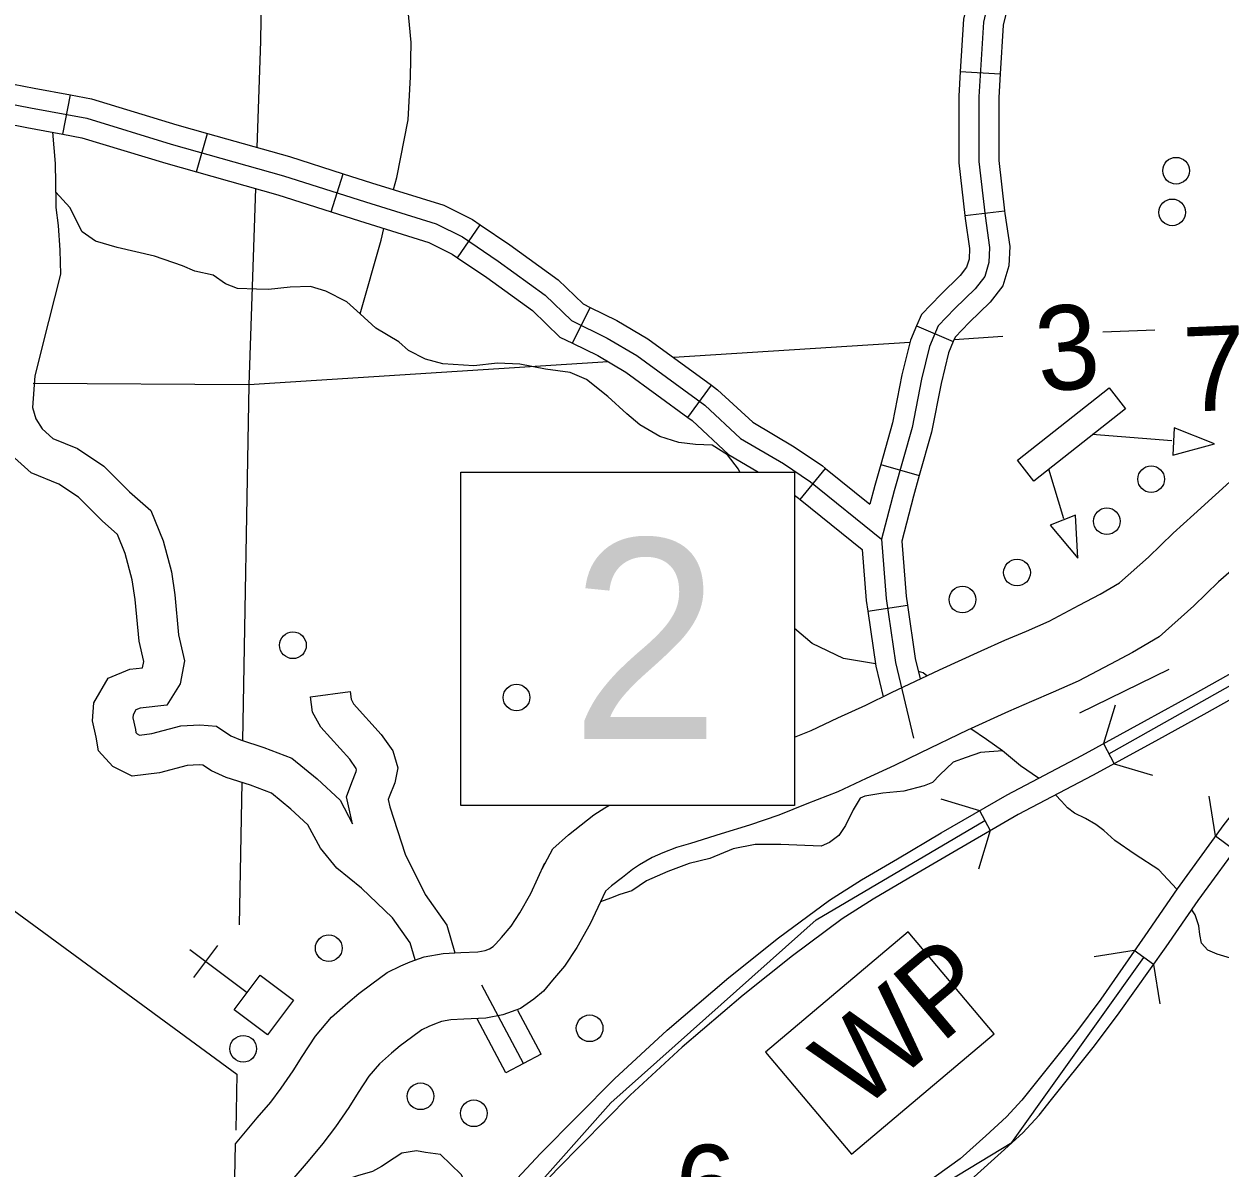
# Model space of a CAD drawing. Extents: x 22866 to 28196, y 1324810 to 1328105.
# Drawn here: x 25197.3 to 25304.9, y 1326082.2 to 1326185.2 of the extents above; entities that cross this region are included whole.
import ezdxf

# ---------------------------------------------------------------- set-up
doc = ezdxf.new("R2010")
doc.units = 0
for name, color, linetype in [('Default', 7, 'Continuous'), ('Level 10', 7, 'Continuous'), ('Level 19', 7, 'Continuous'), ('Level 31', 7, 'Continuous'), ('Level 32', 7, 'Continuous'), ('Level 35', 7, 'Continuous'), ('Level 39', 7, 'Continuous'), ('Level 45', 7, 'Continuous'), ('Level 46', 7, 'Continuous'), ('Level 5', 7, 'Continuous'), ('Level 56', 7, 'Continuous'), ('Level 57', 7, 'Continuous'), ('Level 63', 7, 'Continuous')]:
    doc.layers.add(name, color=color, linetype=linetype)

msp = doc.modelspace()

# ---------------------------------------------------------------- linework, layer by layer
at = {"layer": 'Default'}
for p, q in [((25294.91, 1326119.53), (25321.82, 1326134.66)), ((25268.58, 1326104.59), (25283.76, 1326113.52)), ((25250.12, 1326088.11), (25268.58, 1326104.59)), ((25286.19, 1326084.53), (25298.07, 1326101.19)), ((25233.67, 1326069.64), (25250.12, 1326088.11)), ((25267.72, 1326073.42), (25286.19, 1326084.53))]:
    msp.add_line(p, q, dxfattribs=at)
msp.add_lwpolyline([(25236.63, 1326144.87), (25266.63, 1326144.87), (25266.63, 1326114.87), (25236.63, 1326114.87)], close=True, dxfattribs=at)
msp.add_lwpolyline([(25236.63, 1326144.87), (25266.63, 1326144.87), (25266.63, 1326114.87), (25236.63, 1326114.87)], close=True, dxfattribs=at)
at = {"layer": 'Level 10'}
msp.add_line((25216.19, 1326075.25), (25216.35, 1326084.43), dxfattribs=at)
for points in [[(25184.79, 1326187.58), (25185.09, 1326186.26), (25185.6, 1326185.4), (25187.75, 1326183.63), (25189.56, 1326182.02), (25191.56, 1326180.21), (25193.29, 1326178.96), (25195.91, 1326178.05), (25197.91, 1326177.67), (25202.97, 1326176.72), (25210.58, 1326174.4)], [(25210.58, 1326174.4), (25220.68, 1326171.55), (25228.06, 1326169.19), (25234.41, 1326167.23), (25236.77, 1326166.05), (25239.98, 1326163.85), (25244.22, 1326160.79), (25246.57, 1326158.51), (25249.79, 1326156.94), (25252.46, 1326155.37), (25258.58, 1326150.9), (25261.79, 1326147.91), (25265.64, 1326145.64), (25268.07, 1326143.99), (25274.46, 1326138.83)], [(25266.63, 1326121.02), (25268.14, 1326121.62), (25270.54, 1326122.75), (25273.05, 1326123.91), (25275.36, 1326125.03), (25279.67, 1326127.09), (25283.44, 1326128.8), (25285.57, 1326129.74), (25287.5, 1326130.57), (25289.53, 1326131.46), (25292.25, 1326132.9), (25294.12, 1326133.88), (25295.87, 1326134.92), (25298.47, 1326137.23), (25300.7, 1326139.39), (25302.57, 1326141.06), (25306.45, 1326144.59)], [(25306.59, 1326136.6), (25304.78, 1326134.99), (25302.56, 1326132.84), (25299.44, 1326130.05), (25297.05, 1326128.63), (25295.05, 1326127.59), (25292.15, 1326126.05), (25289.89, 1326125.06), (25287.96, 1326124.23), (25285.89, 1326123.32), (25282.21, 1326121.65), (25277.97, 1326119.62), (25275.62, 1326118.48), (25273.08, 1326117.31), (25270.52, 1326116.11), (25267.74, 1326115.01), (25265.23, 1326114.01), (25262.6, 1326113.11), (25260.05, 1326112.31), (25257.29, 1326111.46), (25256.02, 1326111.08), (25254.8, 1326110.62), (25253.83, 1326110.2), (25252.7, 1326109.53), (25252.06, 1326109.12), (25251.15, 1326108.4), (25250.16, 1326107.64), (25249.63, 1326107.15)], [(25243.95, 1326109.18), (25244.9, 1326110.96), (25246.3, 1326112.24), (25247.45, 1326113.12), (25248.59, 1326114.04), (25249.58, 1326114.65), (25249.95, 1326114.87)], [(25223.54, 1326094.1), (25225, 1326095.83), (25226.47, 1326097.12), (25227.45, 1326097.95), (25228.62, 1326098.82), (25230, 1326099.83), (25231.24, 1326100.44), (25232.08, 1326100.79), (25233.31, 1326101.24), (25235.04, 1326101.56), (25236.62, 1326101.63), (25238.15, 1326101.69), (25238.81, 1326101.82), (25239.21, 1326101.97), (25239.53, 1326102.19), (25239.78, 1326102.41), (25240.29, 1326103), (25241.14, 1326104.02), (25241.94, 1326105.22), (25242.91, 1326106.95), (25244.19, 1326109.7)], [(25249.63, 1326107.15), (25248.25, 1326104.21), (25247.06, 1326102.08), (25245.95, 1326100.42), (25244.88, 1326099.14), (25244.05, 1326098.16), (25243.2, 1326097.43), (25241.98, 1326096.59), (25240.41, 1326096.02), (25238.87, 1326095.72), (25236.89, 1326095.63), (25235.72, 1326095.58), (25234.89, 1326095.43), (25234.26, 1326095.2), (25233.73, 1326094.98), (25233.12, 1326094.68), (25232.18, 1326093.99), (25231.18, 1326093.25), (25230.39, 1326092.58), (25229.3, 1326091.62), (25228.36, 1326090.5)], [(25216.35, 1326084.43), (25218.3, 1326086.76), (25219.53, 1326088.18), (25220.46, 1326089.44), (25221.53, 1326090.99), (25222.35, 1326092.29), (25223.54, 1326094.1)], [(25228.36, 1326090.5), (25227.39, 1326089.04), (25226.55, 1326087.7), (25225.34, 1326085.94), (25224.22, 1326084.44), (25222.88, 1326082.87), (25221.42, 1326081.14), (25219.28, 1326078.62), (25217.76, 1326076.97)]]:
    msp.add_lwpolyline(points, dxfattribs=at)
at = {"layer": 'Level 19'}
for points in [[(25302.72, 1326124.98), (25310.15, 1326129.15), (25315.19, 1326132.18), (25315.37, 1326132.34)], [(25316.47, 1326130.68), (25316.4, 1326130.63), (25311.16, 1326127.38), (25303.72, 1326123.2)], [(25318.65, 1326128.4), (25317.58, 1326127.33), (25314.63, 1326124.17), (25311.4, 1326120.55), (25307.94, 1326116.57), (25305.26, 1326113.16), (25301.05, 1326107.37), (25298.14, 1326103.15), (25294.2, 1326097.43)], [(25295.83, 1326096.2), (25300.06, 1326102.15), (25302.95, 1326106.33), (25307.1, 1326112.03), (25309.67, 1326115.32), (25313.06, 1326119.21), (25316.24, 1326122.79), (25319.05, 1326125.79), (25319.79, 1326126.71)], [(25219.81, 1326056.48), (25218.48, 1326058.03), (25223.62, 1326062.78), (25232.2, 1326071.06), (25233.75, 1326072.77), (25243.8, 1326083.55), (25250.43, 1326090.27), (25255.19, 1326094.64), (25260.72, 1326099.38), (25265.21, 1326102.96), (25269.77, 1326106.36), (25272.66, 1326108.19), (25275.89, 1326110.08), (25279.84, 1326112.41), (25285.78, 1326115.84), (25292.47, 1326119.37), (25298.13, 1326122.46), (25302.72, 1326124.98)], [(25303.72, 1326123.2), (25299.12, 1326120.67), (25293.43, 1326117.57), (25286.76, 1326114.06), (25280.87, 1326110.65), (25276.93, 1326108.32), (25273.72, 1326106.44), (25270.93, 1326104.68), (25266.45, 1326101.34), (25262.02, 1326097.8), (25256.54, 1326093.12), (25251.85, 1326088.8), (25245.28, 1326082.14), (25235.25, 1326071.39), (25233.67, 1326069.64), (25225.02, 1326061.29), (25219.81, 1326056.48)], [(25294.2, 1326097.43), (25292, 1326094.49), (25288.16, 1326089.69), (25287.08, 1326088.34), (25285.72, 1326086.86), (25283.85, 1326085.15), (25281.53, 1326083.06), (25278.23, 1326080.71), (25276.73, 1326079.74), (25274.1, 1326078.22), (25271.69, 1326077.1), (25269.43, 1326076.14), (25264.65, 1326074.56), (25259.94, 1326073), (25255.94, 1326071.72), (25252.61, 1326070.71), (25248.87, 1326069.47), (25245.88, 1326068.29), (25242.81, 1326066.99), (25239.52, 1326065.45), (25236.93, 1326064.23)], [(25237.8, 1326062.38), (25240.39, 1326063.6), (25243.64, 1326065.12), (25246.65, 1326066.4), (25249.57, 1326067.55), (25253.23, 1326068.77), (25256.54, 1326069.77), (25260.58, 1326071.06), (25265.29, 1326072.62), (25270.15, 1326074.23), (25272.53, 1326075.24), (25275.04, 1326076.41), (25277.8, 1326078), (25279.37, 1326079.02), (25282.81, 1326081.46), (25285.22, 1326083.64), (25287.16, 1326085.42), (25288.63, 1326087.01), (25289.75, 1326088.42), (25293.61, 1326093.24), (25295.83, 1326096.2)]]:
    msp.add_lwpolyline(points, dxfattribs=at)
at = {"layer": 'Level 31'}
for points in [[(25299.39, 1326224.03), (25302.07, 1326218.13), (25302.75, 1326215.52), (25302.82, 1326214.29), (25302.48, 1326212.16), (25301.45, 1326210.17), (25298.23, 1326205.78), (25294.18, 1326200.98), (25290.89, 1326198.44), (25289.04, 1326197.2), (25288.01, 1326195.94), (25285.61, 1326191.82), (25284.52, 1326189.15), (25283.63, 1326185.37), (25283.21, 1326178.65), (25283.21, 1326172.82), (25283.78, 1326167.93)], [(25283.78, 1326167.93), (25284.19, 1326165.08), (25284.12, 1326163.75), (25283.75, 1326162.48), (25282.89, 1326161.38), (25281.07, 1326159.6), (25279.57, 1326158.04), (25278.78, 1326156.19), (25278.06, 1326153.24), (25277.21, 1326148.88), (25275.6, 1326143.19), (25274.46, 1326138.83), (25274.88, 1326133.51), (25275.73, 1326127.75), (25277.34, 1326120.92)]]:
    msp.add_lwpolyline(points, dxfattribs=at)
at = {"layer": 'Level 32'}
for p, q in [((25281.55, 1326180.93), (25285.14, 1326180.71)), ((25200.83, 1326175.29), (25201.5, 1326178.83)), ((25212.86, 1326171.89), (25213.84, 1326175.35)), ((25224.95, 1326168.3), (25226.05, 1326171.73)), ((25281.96, 1326167.98), (25285.54, 1326168.39)), ((25236.33, 1326164.17), (25238.37, 1326167.14)), ((25246.67, 1326156.47), (25248.25, 1326159.7)), ((25277.61, 1326158.03), (25280.92, 1326156.62)), ((25257.03, 1326149.8), (25259.16, 1326152.71)), ((25267.16, 1326142.41), (25269.42, 1326145.21)), ((25274.4, 1326145.56), (25277.86, 1326144.58)), ((25273.23, 1326132.37), (25276.79, 1326132.9)), ((25243.85, 1326092.5), (25240.67, 1326090.81))]:
    msp.add_line(p, q, dxfattribs=at)
for points in [[(25284.74, 1326193.89), (25284, 1326192.62), (25282.8, 1326189.7), (25281.84, 1326185.64), (25281.55, 1326180.93)], [(25287.85, 1326192.08), (25287.23, 1326191.03), (25286.24, 1326188.6), (25285.41, 1326185.11), (25285.14, 1326180.71)], [(25190.97, 1326183.17), (25192.7, 1326181.61), (25194.13, 1326180.57), (25196.38, 1326179.8), (25198.25, 1326179.44), (25201.5, 1326178.83)], [(25188.56, 1326180.5), (25190.42, 1326178.81), (25192.44, 1326177.34), (25195.45, 1326176.31), (25197.58, 1326175.9), (25200.83, 1326175.29)], [(25281.55, 1326180.93), (25281.41, 1326178.71), (25281.41, 1326172.72), (25281.96, 1326167.98)], [(25285.14, 1326180.71), (25285.01, 1326178.6), (25285.01, 1326172.92), (25285.54, 1326168.39)], [(25201.5, 1326178.83), (25203.4, 1326178.47), (25211.09, 1326176.13), (25213.84, 1326175.35)], [(25200.83, 1326175.29), (25202.54, 1326174.97), (25210.08, 1326172.68), (25212.86, 1326171.89)], [(25213.84, 1326175.35), (25221.2, 1326173.27), (25226.05, 1326171.73)], [(25212.86, 1326171.89), (25220.17, 1326169.82), (25224.95, 1326168.3)], [(25226.05, 1326171.73), (25228.6, 1326170.91), (25235.09, 1326168.91), (25237.68, 1326167.61), (25238.37, 1326167.14)], [(25224.95, 1326168.3), (25227.52, 1326167.48), (25233.74, 1326165.55), (25235.85, 1326164.5), (25236.33, 1326164.17)], [(25281.96, 1326167.98), (25281.99, 1326167.7), (25282.38, 1326165), (25282.34, 1326164.05), (25282.12, 1326163.32), (25281.54, 1326162.58), (25279.79, 1326160.86), (25278.05, 1326159.05), (25277.61, 1326158.03)], [(25285.54, 1326168.39), (25285.57, 1326168.16), (25286, 1326165.17), (25285.91, 1326163.44), (25285.37, 1326161.64), (25284.24, 1326160.18), (25282.35, 1326158.33), (25281.1, 1326157.03), (25280.92, 1326156.62)], [(25238.37, 1326167.14), (25241.02, 1326165.33), (25245.38, 1326162.18), (25247.62, 1326160.01), (25248.25, 1326159.7)], [(25236.33, 1326164.17), (25238.95, 1326162.38), (25243.06, 1326159.41), (25245.53, 1326157.02), (25246.67, 1326156.47)], [(25248.25, 1326159.7), (25250.64, 1326158.53), (25253.45, 1326156.88), (25259.16, 1326152.71)], [(25277.61, 1326158.03), (25277.07, 1326156.76), (25276.3, 1326153.63), (25275.45, 1326149.3), (25274.4, 1326145.56)], [(25246.67, 1326156.47), (25248.94, 1326155.36), (25251.47, 1326153.87), (25257.03, 1326149.8)], [(25280.92, 1326156.62), (25280.5, 1326155.62), (25279.82, 1326152.85), (25278.96, 1326148.46), (25277.86, 1326144.58)], [(25259.16, 1326152.71), (25259.72, 1326152.29), (25262.88, 1326149.37), (25266.6, 1326147.16), (25269.14, 1326145.44), (25269.42, 1326145.21)], [(25257.03, 1326149.8), (25257.43, 1326149.51), (25260.71, 1326146.46), (25263.4, 1326144.87)], [(25269.42, 1326145.21), (25273.42, 1326141.98)], [(25274.4, 1326145.56), (25273.86, 1326143.66), (25273.42, 1326141.98)], [(25277.86, 1326144.58), (25277.33, 1326142.72), (25276.28, 1326138.67), (25276.67, 1326133.71), (25276.79, 1326132.9)], [(25266.63, 1326142.79), (25267, 1326142.54), (25267.16, 1326142.41)], [(25267.16, 1326142.41), (25272.73, 1326137.91)], [(25272.73, 1326137.91), (25273.09, 1326133.31), (25273.23, 1326132.37)], [(25273.23, 1326132.37), (25273.96, 1326127.41), (25274.61, 1326124.66)], [(25276.79, 1326132.9), (25277.5, 1326128.09), (25277.93, 1326126.26)], [(25242.26, 1326091.66), (25238.51, 1326098.71)], [(25240.67, 1326090.81), (25238.08, 1326095.68)], [(25243.85, 1326092.5), (25241.76, 1326096.43)]]:
    msp.add_lwpolyline(points, dxfattribs=at)
at = {"layer": 'Level 35'}
for points in [[(25230.58, 1326170.3), (25230.86, 1326171.39), (25231.9, 1326176.57), (25232.11, 1326180.45), (25232.16, 1326183.53), (25231.8, 1326187.35), (25231.27, 1326188.22), (25229.65, 1326189.84), (25228.19, 1326191.15), (25226.99, 1326193.14), (25224.27, 1326197.69), (25222.75, 1326201.93)], [(25226.37, 1326160.19), (25224.47, 1326161.17), (25223.09, 1326161.57), (25221.27, 1326161.52), (25219.32, 1326161.3), (25218.25, 1326161.34), (25216.52, 1326161.39), (25215.45, 1326161.83), (25214.34, 1326162.59), (25212.7, 1326162.95), (25211.59, 1326163.43), (25209.06, 1326164.32), (25205.72, 1326165.08), (25203.77, 1326165.66), (25202.57, 1326166.5), (25201.46, 1326168.68), (25200.18, 1326170.08)], [(25227.57, 1326159.12), (25229.45, 1326165.74), (25229.71, 1326166.8)], [(25261.72, 1326144.87), (25261.59, 1326145.14), (25260.62, 1326146.43), (25259.24, 1326147.31), (25257.73, 1326147.36), (25256.22, 1326147.54), (25254.53, 1326148.07), (25252.71, 1326149.14), (25251.55, 1326150.12), (25249.86, 1326151.67), (25247.92, 1326153.21), (25246.45, 1326153.83), (25244.23, 1326154.14), (25241.92, 1326154.59), (25239.92, 1326154.67), (25237.79, 1326154.45), (25234.99, 1326154.63), (25233.44, 1326155.03), (25231.93, 1326155.83), (25231.04, 1326156.59), (25228.99, 1326157.83), (25227.57, 1326159.12), (25226.37, 1326160.19)], [(25273.93, 1326127.61), (25271.05, 1326128.11), (25268.21, 1326129.44), (25266.63, 1326130.81)], [(25278.55, 1326126.54), (25278.21, 1326126.81), (25277.78, 1326126.92)], [(25288.57, 1326117.32), (25286.95, 1326118.43), (25285.34, 1326119.8), (25283.9, 1326120.81), (25282.49, 1326121.78)], [(25285.34, 1326119.8), (25283.37, 1326119.63), (25282.09, 1326119.2), (25280.92, 1326118.76), (25279.72, 1326117.62), (25279.05, 1326116.95), (25278.31, 1326116.65), (25276.47, 1326116.15), (25274.59, 1326115.98), (25272.95, 1326115.71), (25272.55, 1326115.54), (25271.91, 1326114.47), (25271.21, 1326113.06), (25270.61, 1326112.16), (25269.77, 1326111.55), (25269.03, 1326111.22)], [(25290.64, 1326115.25), (25290.1, 1326115.82)], [(25295.45, 1326111.71), (25294.46, 1326112.61), (25293.73, 1326113.16), (25292.81, 1326113.71), (25291.82, 1326114.18), (25291.19, 1326114.65), (25290.64, 1326115.25)], [(25301.03, 1326107.35), (25299.4, 1326109.07), (25297.28, 1326110.45), (25295.45, 1326111.71)], [(25269.03, 1326111.22), (25266.86, 1326111.29), (25265.42, 1326111.35), (25263.11, 1326111.35), (25261.13, 1326110.98), (25259.02, 1326110.11), (25257.15, 1326109.64), (25255.24, 1326108.94), (25253.33, 1326108.1), (25251.99, 1326107.2), (25250.92, 1326106.86), (25250.08, 1326106.52)], [(25250.08, 1326106.52), (25249.18, 1326106.2)], [(25303.02, 1326104.05), (25302.69, 1326105.04), (25302.37, 1326105.49)], [(25307.83, 1326095.74), (25307.21, 1326096.73), (25306.87, 1326097.75), (25306.87, 1326098.4), (25307.08, 1326099.14), (25306.97, 1326099.76), (25306.5, 1326100.52), (25305.85, 1326101.12), (25304.64, 1326101.49), (25303.83, 1326101.86), (25303.26, 1326102.48), (25303.1, 1326103.27), (25303.02, 1326104.05)]]:
    msp.add_lwpolyline(points, dxfattribs=at)
at = {"layer": 'Level 39'}
for p, q in [((25295.47, 1326123.9), (25294.43, 1326120.44)), ((25294.43, 1326120.44), (25295.39, 1326118.63)), ((25295.39, 1326118.63), (25298.85, 1326117.59)), ((25279.81, 1326115.48), (25283.28, 1326114.43)), ((25304.5, 1326112.13), (25303.94, 1326115.7)), ((25283.28, 1326114.43), (25284.24, 1326112.62)), ((25284.24, 1326112.62), (25283.18, 1326109.13)), ((25304.5, 1326112.13), (25306.25, 1326110.85)), ((25297.2, 1326101.82), (25293.6, 1326101.24)), ((25298.93, 1326100.56), (25297.2, 1326101.82)), ((25298.93, 1326100.56), (25299.5, 1326097.02))]:
    msp.add_line(p, q, dxfattribs=at)
at = {"layer": 'Level 45'}
msp.add_lwpolyline([(25236.82, 1326081.34), (25236.64, 1326081.66), (25234.79, 1326083.46), (25233.45, 1326083.63), (25232.63, 1326083.79), (25231.33, 1326083.57), (25230.64, 1326083.13), (25229.5, 1326082.39), (25228.69, 1326081.93), (25227.34, 1326081.53), (25226.89, 1326081.38)], dxfattribs=at)
at = {"layer": 'Level 46'}
for points in [[(25199.9, 1326175.47), (25200.13, 1326172.64), (25200.2, 1326169.14), (25200.2, 1326168.68), (25200.4, 1326167.08), (25200.54, 1326164.85), (25200.62, 1326162.7), (25199.52, 1326158.44), (25198.31, 1326153.54), (25198.08, 1326150.7), (25198.39, 1326149.67), (25198.96, 1326148.78), (25199.92, 1326147.91), (25202.15, 1326146.99), (25204.52, 1326145.41), (25206.82, 1326143.11), (25208.75, 1326141.41), (25209.85, 1326138.68), (25210.6, 1326135.91), (25210.9, 1326133.83), (25211.24, 1326130.24), (25211.78, 1326127.9), (25211.37, 1326125.82), (25210.19, 1326123.9), (25207.77, 1326123.62), (25207.39, 1326123.47), (25207.14, 1326123.04), (25207.12, 1326122.75), (25207.35, 1326121.72), (25207.4, 1326121.44), (25207.52, 1326121.31), (25207.71, 1326121.21), (25208.84, 1326121.34), (25211.45, 1326122.05), (25213.14, 1326122.13), (25214.63, 1326122.02), (25215.92, 1326121.15), (25216.8, 1326120.77), (25218.9, 1326120.09), (25221.43, 1326119.14), (25223.71, 1326117.26), (25225.77, 1326115.36), (25226.89, 1326113.23)], [(25232.51, 1326100.97), (25232.07, 1326102.52), (25230.49, 1326104.76), (25227.69, 1326107.42), (25225.46, 1326109.22), (25223.99, 1326111.03), (25222.87, 1326113.13), (25221.34, 1326114.55), (25219.6, 1326115.98), (25217.71, 1326116.69), (25215.52, 1326117.4), (25214.19, 1326117.98), (25213.41, 1326118.5), (25213.1, 1326118.53), (25212.02, 1326118.47), (25209.52, 1326117.8), (25207.06, 1326117.51), (25205.31, 1326118.39), (25204.04, 1326119.78), (25203.82, 1326121.01), (25203.49, 1326122.48), (25203.61, 1326124.12), (25204.89, 1326126.33), (25206.86, 1326127.14), (25207.98, 1326127.27), (25208.1, 1326127.84), (25207.68, 1326129.66), (25207.32, 1326133.4), (25207.07, 1326135.19), (25206.43, 1326137.54), (25205.74, 1326139.27), (25204.35, 1326140.48), (25202.23, 1326142.61), (25200.45, 1326143.79), (25197.98, 1326144.81), (25196.18, 1326146.43)], [(25226.89, 1326113.23), (25226.35, 1326115.66), (25226.82, 1326116.95), (25227.22, 1326117.94), (25227.25, 1326118.07), (25227.21, 1326118.21), (25226.64, 1326119.03), (25224.03, 1326121.92), (25223.28, 1326123.27), (25223.09, 1326124.66), (25226.66, 1326125.13)], [(25226.66, 1326125.13), (25226.76, 1326124.43), (25226.98, 1326124.03), (25229.46, 1326121.27), (25230.5, 1326119.78), (25230.95, 1326118.25), (25230.69, 1326116.91), (25230.18, 1326115.66), (25230.1, 1326115.42), (25230.24, 1326114.75), (25231.61, 1326110.49), (25233.4, 1326106.87)], [(25233.4, 1326106.87), (25235.37, 1326104.1), (25236.08, 1326101.6)]]:
    msp.add_lwpolyline(points, dxfattribs=at)
at = {"layer": 'Level 5'}
for points in [[(25219.62, 1326278.67), (25219.28, 1326229.03), (25218.59, 1326183.67), (25218.27, 1326174.1)], [(25218.14, 1326170.4), (25217.55, 1326152.73)], [(25285.39, 1326157.07), (25281, 1326156.79)], [(25299.06, 1326157.66), (25294.37, 1326157.46)], [(25277.01, 1326156.53), (25255.78, 1326155.18)], [(25249.89, 1326154.8), (25217.55, 1326152.73)], [(25217.55, 1326152.73), (25198.14, 1326152.85)], [(25217.55, 1326152.73), (25216.99, 1326120.69)], [(25216.92, 1326116.95), (25216.69, 1326104.13)], [(25216.46, 1326090.68), (25216.37, 1326085.64)]]:
    msp.add_lwpolyline(points, dxfattribs=at)
at = {"layer": 'Level 56'}
for p, q in [((25300.58, 1326147.69), (25293.4, 1326148.27)), ((25290.86, 1326140.67), (25289.51, 1326145.13))]:
    msp.add_line(p, q, dxfattribs=at)
for points in [[(25288.16, 1326144.07), (25286.68, 1326145.96), (25294.93, 1326152.45), (25296.42, 1326150.56)], [(25300.8, 1326148.85), (25300.66, 1326146.41), (25304.4, 1326147.41)], [(25291.92, 1326141), (25289.64, 1326140.11), (25292.11, 1326137.13)]]:
    msp.add_lwpolyline(points, close=True, dxfattribs=at)
msp.add_lwpolyline([(25292.3, 1326123.22), (25300.33, 1326127.13)], dxfattribs=at)
for centre in [(25300.96, 1326172), (25300.61, 1326168.25), (25298.72, 1326144.24), (25294.73, 1326140.45), (25286.65, 1326135.83), (25281.74, 1326133.4), (25221.52, 1326129.29), (25241.63, 1326124.59), (25224.74, 1326102.03), (25248.21, 1326094.82), (25217.05, 1326092.98), (25233, 1326088.7), (25237.79, 1326087.17)]:
    msp.add_circle(centre, 1.2, dxfattribs=at)
at = {"layer": 'Level 57'}
for p, q in [((25212.6, 1326099.4), (25214.76, 1326102.28)), ((25212.24, 1326101.92), (25217.41, 1326098.04))]:
    msp.add_line(p, q, dxfattribs=at)
for points in [[(25284.6, 1326094.32), (25276.86, 1326103.5), (25264.02, 1326092.67)], [(25264.02, 1326092.67), (25271.75, 1326083.49), (25284.6, 1326094.32)]]:
    msp.add_lwpolyline(points, dxfattribs=at)
msp.add_lwpolyline([(25219.24, 1326094.24), (25216.24, 1326096.48), (25218.57, 1326099.59), (25221.57, 1326097.35)], close=True, dxfattribs=at)
at = {"layer": 'Level 63'}
msp.add_line((25174.69, 1326121.39), (25216.46, 1326090.68), dxfattribs=at)

# ---------------------------------------------------------------- texts
at = {"layer": 'Default'}
msp.add_text('2', height=18, dxfattribs=at).set_placement((25246.52, 1326120.87))
at = {"layer": 'Level 56'}
for s, rotation, p in [('3', 5.7169, (25288.72, 1326152.04)), ('7', 2.3881, (25301.75, 1326150.29)), ('6', 4.579, (25256.25, 1326076.51))]:
    msp.add_text(s, height=7.6, rotation=rotation, dxfattribs=at).set_placement(p)
at = {"layer": 'Level 57'}
msp.add_text('WP', height=7.605, rotation=40.1287, dxfattribs=at).set_placement((25272.47, 1326087.18))

doc.saveas('drawing.dxf')
